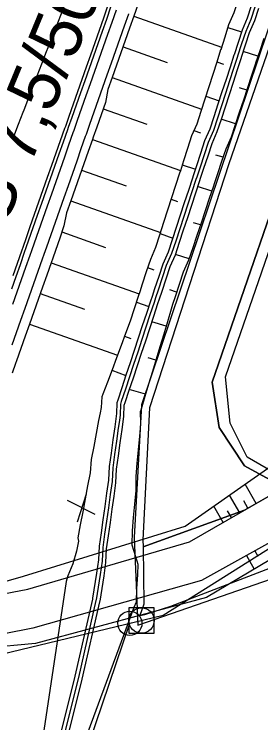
# Model space of a CAD drawing. Extents: x -439827 to -439102, y -1131353 to -1129707.
# Drawn here: x -439604 to -439584.6, y -1130402 to -1130346.4 of the extents above; entities that cross this region are included whole.
import ezdxf

# ---------------------------------------------------------------- set-up
doc = ezdxf.new("R2010")
doc.units = 0
for name, color, linetype in [('Vrstva 1', 7, 'Continuous'), ('Vrstva 10', 7, 'Continuous'), ('Vrstva 11', 7, 'Continuous'), ('Vrstva 13', 7, 'Continuous'), ('Vrstva 15', 7, 'Continuous'), ('Vrstva 2', 7, 'Continuous'), ('Vrstva 29', 7, 'Continuous'), ('Vrstva 4', 7, 'Continuous'), ('Vrstva 44', 7, 'Continuous'), ('Vrstva 45', 7, 'Continuous'), ('Vrstva 52', 7, 'Continuous'), ('Vrstva 8', 7, 'Continuous'), ('Vrstva 9', 7, 'Continuous')]:
    doc.layers.add(name, color=color, linetype=linetype)

msp = doc.modelspace()

# ---------------------------------------------------------------- linework, layer by layer
at = {"layer": 'Vrstva 1'}
for points in [[(-439577.819, -1130295.088), (-439580.971, -1130303.59), (-439578.01, -1130302.539), (-439576.29, -1130302.252), (-439569.317, -1130306.837), (-439584.028, -1130347.627), (-439593.963, -1130377.05), (-439594.536, -1130387.462), (-439594.249, -1130394.34), (-439583.741, -1130390.71), (-439571.132, -1130382.304), (-439541.901, -1130357.085)], [(-439545.626, -1130351.066), (-439561.77, -1130361.383), (-439575.813, -1130377.718), (-439582.499, -1130382.972), (-439585.652, -1130381.157), (-439586.989, -1130378.483), (-439587.371, -1130374.853), (-439572.851, -1130332.916), (-439565.018, -1130320.116), (-439560.242, -1130316.963), (-439559.286, -1130315.53), (-439524.992, -1130313.524)]]:
    msp.add_lwpolyline(points, dxfattribs=at)
at = {"layer": 'Vrstva 10'}
for p, q in [((-439584.948, -1130384.776), (-439585.82, -1130383.256)), ((-439586.25, -1130385.522), (-439587.054, -1130384.12)), ((-439585.6, -1130385.148), (-439585.936, -1130384.564)), ((-439587.55, -1130386.268), (-439588.288, -1130384.984)), ((-439586.9, -1130385.896), (-439587.208, -1130385.358)), ((-439585.056, -1130388.502), (-439584.822, -1130388.926)), ((-439585.712, -1130388.864), (-439585.116, -1130389.944))]:
    msp.add_line(p, q, dxfattribs=at)
at = {"layer": 'Vrstva 11'}
for points in [[(-439614.54, -1130393.736), (-439602.886, -1130391.502), (-439590.194, -1130387.786), (-439581.31, -1130382.686), (-439571.73, -1130375.574), (-439563.408, -1130366.438), (-439554.968, -1130359.058), (-439538.066, -1130350.036), (-439518.176, -1130342.266)], [(-439517.844, -1130344.818), (-439537.232, -1130352.412), (-439553.102, -1130361.278), (-439561.554, -1130368.442), (-439569.834, -1130377.42), (-439579.582, -1130385.476), (-439589.25, -1130390.818), (-439602.494, -1130394.582), (-439614.18, -1130396.886)]]:
    msp.add_lwpolyline(points, dxfattribs=at)
at = {"layer": 'Vrstva 13'}
for p, q in [((-439598.318, -1130384.054), (-439599.028, -1130386.242)), ((-439597.6, -1130385.652), (-439599.772, -1130384.552))]:
    msp.add_line(p, q, dxfattribs=at)
at = {"layer": 'Vrstva 15'}
for p, q in [((-439594.569, -1130346.526), (-439587.676, -1130348.955)), ((-439587.182, -1130347.413), (-439586.104, -1130347.758)), ((-439595.418, -1130348.935), (-439591.938, -1130350.161)), ((-439584.822, -1130349.679), (-439585.975, -1130349.298)), ((-439588.05, -1130350.118), (-439587.518, -1130350.292)), ((-439596.268, -1130351.345), (-439589.241, -1130353.817)), ((-439585.701, -1130352.335), (-439586.272, -1130352.148)), ((-439588.92, -1130352.822), (-439587.869, -1130353.172)), ((-439596.972, -1130353.794), (-439593.544, -1130355.004)), ((-439586.581, -1130354.991), (-439587.713, -1130354.623)), ((-439589.842, -1130355.508), (-439589.322, -1130355.684)), ((-439597.821, -1130356.204), (-439590.902, -1130358.643)), ((-439587.56, -1130357.609), (-439588.119, -1130357.429)), ((-439598.67, -1130358.613), (-439595.18, -1130359.843)), ((-439590.757, -1130358.196), (-439589.735, -1130358.548)), ((-439588.445, -1130360.263), (-439589.552, -1130359.91)), ((-439591.633, -1130360.899), (-439591.129, -1130361.076)), ((-439599.52, -1130361.023), (-439592.479, -1130363.502)), ((-439589.331, -1130362.917), (-439589.879, -1130362.744)), ((-439600.224, -1130363.472), (-439596.792, -1130364.684)), ((-439592.511, -1130363.601), (-439591.515, -1130363.957)), ((-439590.22, -1130365.57), (-439591.304, -1130365.23)), ((-439601.073, -1130365.882), (-439594.152, -1130368.324)), ((-439593.481, -1130366.268), (-439592.991, -1130366.447)), ((-439591.206, -1130368.185), (-439591.741, -1130368.019)), ((-439601.922, -1130368.291), (-439598.444, -1130369.518)), ((-439594.363, -1130368.969), (-439593.397, -1130369.328)), ((-439602.771, -1130370.701), (-439595.843, -1130373.143)), ((-439592.029, -1130370.859), (-439593.158, -1130370.512)), ((-439595.295, -1130371.653), (-439594.794, -1130371.842)), ((-439592.836, -1130373.538), (-439593.438, -1130373.354)), ((-439596.288, -1130374.315), (-439595.192, -1130374.732)), ((-439593.649, -1130376.215), (-439594.925, -1130375.827))]:
    msp.add_line(p, q, dxfattribs=at)
at = {"layer": 'Vrstva 29'}
msp.add_lwpolyline([(-439594.968, -1130394.973), (-439592.968, -1130394.973), (-439592.968, -1130392.973), (-439594.968, -1130392.973)], close=True, dxfattribs=at)
msp.add_lwpolyline([(-439594.968, -1130394.973), (-439592.968, -1130394.973), (-439592.968, -1130392.973), (-439594.968, -1130392.973)], close=True, dxfattribs=at)
msp.add_lwpolyline([(-439645.6, -1130403.853), (-439644.872, -1130403.698), (-439603.72, -1130417.411), (-439603.446, -1130417.268), (-439600.7, -1130411.455), (-439599.692, -1130408.398), (-439594.881, -1130394.192), (-439593.968, -1130393.973)], dxfattribs=at)
msp.add_lwpolyline([(-439645.6, -1130403.853), (-439644.872, -1130403.698), (-439603.72, -1130417.411), (-439603.446, -1130417.268), (-439600.7, -1130411.455), (-439599.692, -1130408.398), (-439594.881, -1130394.192), (-439593.968, -1130393.973)], dxfattribs=at)
for centre, radius in [((-439593.968, -1130393.973), 1), ((-439593.968, -1130393.973), 1), ((-439594.881, -1130394.192), 0.95), ((-439594.881, -1130394.192), 0.95)]:
    msp.add_circle(centre, radius, dxfattribs=at)
at = {"layer": 'Vrstva 4'}
for points in [[(-439559.98, -1130315.123), (-439561.071, -1130316.673), (-439565.58, -1130320.223), (-439568.805, -1130324.53), (-439573.789, -1130332.956), (-439588.419, -1130375.264), (-439587.856, -1130378.814), (-439585.86, -1130381.827), (-439582.761, -1130383.539), (-439582.76, -1130383.539), (-439581.08, -1130382.59), (-439575.74, -1130378.42), (-439561.14, -1130361.82), (-439544.24, -1130351.07), (-439531.53, -1130345.11), (-439529.72, -1130344.26), (-439519.35, -1130339.39), (-439519.98, -1130330.32), (-439521.73, -1130320.56), (-439525.556, -1130312.748), (-439559.98, -1130315.123)], [(-439581.59, -1130342.25), (-439587.1, -1130358.13), (-439593.34, -1130377.27), (-439593.85, -1130387.65), (-439593.84, -1130388.2), (-439585.88, -1130385.3), (-439582.761, -1130383.539), (-439585.86, -1130381.827), (-439587.856, -1130378.814), (-439588.419, -1130375.264), (-439573.789, -1130332.956)], [(-439581.59, -1130342.25), (-439587.1, -1130358.13), (-439593.34, -1130377.27), (-439593.85, -1130387.65), (-439593.84, -1130388.2), (-439585.88, -1130385.3), (-439582.761, -1130383.539), (-439585.86, -1130381.827), (-439587.856, -1130378.814), (-439588.419, -1130375.264), (-439573.789, -1130332.956)], [(-439544.24, -1130351.07), (-439561.14, -1130361.82), (-439575.74, -1130378.42), (-439581.08, -1130382.59), (-439582.761, -1130383.539), (-439585.88, -1130385.3), (-439593.84, -1130388.2), (-439593.78, -1130392.68), (-439594.1, -1130393.57)], [(-439594.1, -1130393.57), (-439593.7, -1130393.5), (-439591.67, -1130392.84), (-439588.25, -1130391.525), (-439583.84, -1130389.83), (-439572.44, -1130382.24), (-439542.04, -1130355.91)]]:
    msp.add_lwpolyline(points, dxfattribs=at)
at = {"layer": 'Vrstva 44'}
msp.add_circle((-439594.881, -1130394.192), 0.95, dxfattribs=at)
at = {"layer": 'Vrstva 45'}
msp.add_lwpolyline([(-439594.968, -1130394.973), (-439592.968, -1130394.973), (-439592.968, -1130392.973), (-439594.968, -1130392.973)], close=True, dxfattribs=at)
msp.add_lwpolyline([(-439645.6, -1130403.853), (-439644.872, -1130403.698), (-439603.72, -1130417.411), (-439603.446, -1130417.268), (-439600.7, -1130411.455), (-439599.692, -1130408.398), (-439594.881, -1130394.192), (-439593.968, -1130393.973)], dxfattribs=at)
msp.add_circle((-439593.968, -1130393.973), 1, dxfattribs=at)
at = {"layer": 'Vrstva 52'}
msp.add_lwpolyline([(-439714.406, -1130412.208), (-439698.562, -1130412.132), (-439686.994, -1130411.394), (-439659.688, -1130406.848), (-439631.008, -1130400.752), (-439604.978, -1130396.618), (-439592.268, -1130393.564), (-439572.812, -1130381.312), (-439556.454, -1130367.154), (-439543.11, -1130355.814), (-439532.998, -1130352.028), (-439506.332, -1130342.096), (-439504.524, -1130343.242), (-439465.198, -1130328.028)], dxfattribs=at)
at = {"layer": 'Vrstva 8'}
for points in [[(-439567.787, -1130292.563), (-439570.478, -1130300.099), (-439571.151, -1130301.984), (-439574.419, -1130311.441), (-439577.66, -1130320.91), (-439581.001, -1130330.339), (-439584.519, -1130339.7), (-439585.609, -1130342.815), (-439585.78, -1130343.353), (-439586.092, -1130344.327), (-439586.403, -1130345.3), (-439586.715, -1130346.274), (-439587.117, -1130347.212), (-439587.429, -1130348.185), (-439587.742, -1130349.159), (-439587.747, -1130349.174), (-439588.054, -1130350.132), (-439588.367, -1130351.105), (-439588.68, -1130352.078), (-439588.994, -1130353.051), (-439589.307, -1130354.024), (-439589.621, -1130354.996)], [(-439596.391, -1130345.832), (-439596.726, -1130346.78), (-439597.065, -1130347.743), (-439597.404, -1130348.706), (-439597.744, -1130349.669), (-439598.083, -1130350.632), (-439598.422, -1130351.594), (-439598.762, -1130352.557), (-439599.101, -1130353.52), (-439599.44, -1130354.483), (-439599.717, -1130355.268), (-439599.78, -1130355.446), (-439600.119, -1130356.409), (-439600.458, -1130357.371), (-439600.798, -1130358.334), (-439601.137, -1130359.297), (-439601.476, -1130360.26), (-439601.815, -1130361.223), (-439602.155, -1130362.185), (-439602.494, -1130363.148), (-439602.833, -1130364.111), (-439603.042, -1130364.704), (-439603.173, -1130365.074), (-439603.512, -1130366.037), (-439603.851, -1130367), (-439604.191, -1130367.962)], [(-439594.228, -1130345.558), (-439594.567, -1130346.521), (-439594.573, -1130346.535), (-439594.907, -1130347.483), (-439595.246, -1130348.446), (-439595.585, -1130349.409), (-439595.925, -1130350.372), (-439596.264, -1130351.335), (-439596.603, -1130352.297), (-439596.803, -1130353.314), (-439597.142, -1130354.277), (-439597.481, -1130355.24), (-439597.758, -1130356.025), (-439597.821, -1130356.203), (-439598.16, -1130357.166), (-439598.499, -1130358.128), (-439598.839, -1130359.091), (-439599.178, -1130360.054), (-439599.517, -1130361.017), (-439599.857, -1130361.98), (-439600.056, -1130362.997), (-439600.395, -1130363.959), (-439600.735, -1130364.922), (-439600.944, -1130365.515), (-439601.074, -1130365.885), (-439601.413, -1130366.848), (-439601.753, -1130367.811), (-439602.092, -1130368.774), (-439602.431, -1130369.736), (-439602.771, -1130370.699), (-439603.11, -1130371.662), (-439603.449, -1130372.625), (-439603.789, -1130373.588), (-439603.864, -1130373.803), (-439604.119, -1130374.554)], [(-439596.625, -1130345.742), (-439596.959, -1130346.69), (-439597.298, -1130347.653), (-439597.637, -1130348.616), (-439597.977, -1130349.579), (-439598.316, -1130350.541), (-439598.655, -1130351.504), (-439598.995, -1130352.467), (-439599.334, -1130353.43), (-439599.673, -1130354.393), (-439599.95, -1130355.178), (-439600.013, -1130355.356), (-439600.352, -1130356.318), (-439600.691, -1130357.281), (-439601.031, -1130358.244), (-439601.37, -1130359.207), (-439601.709, -1130360.17), (-439602.049, -1130361.132), (-439602.388, -1130362.095), (-439602.727, -1130363.058), (-439603.067, -1130364.021), (-439603.276, -1130364.614), (-439603.406, -1130364.984), (-439603.745, -1130365.947), (-439604.085, -1130366.909)], [(-439599.973, -1130345.525), (-439600.34, -1130346.477), (-439600.708, -1130347.429), (-439601.076, -1130348.381), (-439601.444, -1130349.332), (-439601.812, -1130350.284), (-439602.18, -1130351.236), (-439602.548, -1130352.188), (-439602.916, -1130353.14), (-439603.216, -1130353.916), (-439603.284, -1130354.091), (-439603.651, -1130355.043), (-439604.019, -1130355.995)], [(-439585.335, -1130345.713), (-439585.65, -1130346.685), (-439586.059, -1130347.621), (-439586.376, -1130348.593), (-439586.692, -1130349.565), (-439586.697, -1130349.58), (-439587.009, -1130350.536), (-439587.325, -1130351.508), (-439587.643, -1130352.479), (-439587.96, -1130353.45), (-439588.277, -1130354.422), (-439588.595, -1130355.393), (-439589.007, -1130356.328), (-439589.325, -1130357.299), (-439589.644, -1130358.269), (-439589.904, -1130359.061), (-439589.962, -1130359.24), (-439590.281, -1130360.211), (-439590.601, -1130361.181), (-439590.92, -1130362.152)], [(-439585.055, -1130345.821), (-439585.37, -1130346.793), (-439585.78, -1130347.729), (-439586.096, -1130348.701), (-439586.412, -1130349.673), (-439586.417, -1130349.688), (-439586.729, -1130350.644), (-439587.046, -1130351.616), (-439587.363, -1130352.587), (-439587.68, -1130353.559), (-439587.998, -1130354.53), (-439588.315, -1130355.501), (-439588.727, -1130356.436), (-439589.045, -1130357.407), (-439589.364, -1130358.378), (-439589.624, -1130359.169), (-439589.683, -1130359.348), (-439590.002, -1130360.319), (-439590.321, -1130361.29), (-439590.64, -1130362.26)], [(-439584.775, -1130345.93), (-439585.091, -1130346.902), (-439585.5, -1130347.837), (-439585.816, -1130348.809), (-439586.132, -1130349.781), (-439586.137, -1130349.796), (-439586.449, -1130350.752), (-439586.766, -1130351.724), (-439587.083, -1130352.695), (-439587.4, -1130353.667), (-439587.718, -1130354.638), (-439588.036, -1130355.609), (-439588.447, -1130356.544), (-439588.765, -1130357.515), (-439589.084, -1130358.486), (-439589.344, -1130359.277), (-439589.403, -1130359.457), (-439589.722, -1130360.427), (-439590.041, -1130361.398), (-439590.361, -1130362.368)], [(-439594.987, -1130346.358), (-439594.992, -1130346.373), (-439595.326, -1130347.321), (-439595.666, -1130348.284), (-439596.005, -1130349.247), (-439596.344, -1130350.21), (-439596.684, -1130351.172), (-439597.023, -1130352.135), (-439597.362, -1130353.098), (-439597.702, -1130354.061), (-439598.041, -1130355.024), (-439598.318, -1130355.809), (-439598.38, -1130355.986), (-439598.72, -1130356.949), (-439599.059, -1130357.912), (-439599.398, -1130358.875), (-439599.738, -1130359.838), (-439600.077, -1130360.801), (-439600.416, -1130361.763), (-439600.756, -1130362.726), (-439601.095, -1130363.689), (-439601.434, -1130364.652), (-439601.643, -1130365.244), (-439601.774, -1130365.615), (-439602.113, -1130366.578), (-439602.452, -1130367.54), (-439602.792, -1130368.503), (-439603.131, -1130369.466), (-439603.47, -1130370.429), (-439603.81, -1130371.392), (-439604.149, -1130372.354)], [(-439604.074, -1130369.134), (-439603.735, -1130368.171), (-439603.396, -1130367.208), (-439603.056, -1130366.245), (-439602.717, -1130365.283), (-439602.586, -1130364.912), (-439602.378, -1130364.32), (-439602.038, -1130363.357), (-439601.699, -1130362.394), (-439601.36, -1130361.431), (-439601.02, -1130360.468), (-439600.681, -1130359.506), (-439600.342, -1130358.543), (-439600.002, -1130357.58), (-439599.663, -1130356.617), (-439599.324, -1130355.654), (-439599.261, -1130355.476), (-439598.984, -1130354.692), (-439598.645, -1130353.729), (-439598.306, -1130352.766), (-439597.966, -1130351.803), (-439597.627, -1130350.84), (-439597.288, -1130349.877), (-439596.948, -1130348.915), (-439596.609, -1130347.952), (-439596.27, -1130346.989), (-439595.935, -1130346.041)], [(-439584.359, -1130348.278), (-439584.679, -1130349.248), (-439585, -1130350.219), (-439585.005, -1130350.234), (-439585.321, -1130351.188), (-439585.642, -1130352.158), (-439585.963, -1130353.128), (-439586.285, -1130354.098), (-439586.607, -1130355.067), (-439586.929, -1130356.037), (-439587.347, -1130356.969), (-439587.67, -1130357.938), (-439587.993, -1130358.908), (-439588.256, -1130359.698), (-439588.316, -1130359.877), (-439588.639, -1130360.846), (-439588.963, -1130361.815), (-439589.287, -1130362.783), (-439589.611, -1130363.752), (-439589.935, -1130364.721), (-439590.26, -1130365.689), (-439590.681, -1130366.62), (-439591.006, -1130367.589), (-439591.331, -1130368.557), (-439591.527, -1130369.155), (-439591.638, -1130369.532), (-439591.927, -1130370.515), (-439592.218, -1130371.496), (-439592.514, -1130372.476), (-439592.811, -1130373.455), (-439593.108, -1130374.434), (-439593.405, -1130375.413), (-439593.703, -1130376.392), (-439593.997, -1130377.373), (-439594.059, -1130377.593), (-439594.036, -1130378.451), (-439594.076, -1130378.89), (-439594.132, -1130379.508), (-439594.227, -1130380.565), (-439594.323, -1130381.622), (-439594.42, -1130382.679), (-439594.419, -1130383.773), (-439594.516, -1130384.83), (-439594.613, -1130385.886), (-439594.71, -1130386.943), (-439594.721, -1130388.032), (-439594.332, -1130389.277), (-439594.244, -1130389.546), (-439594.286, -1130390.388), (-439594.36, -1130391.454), (-439594.377, -1130392.541), (-439594.567, -1130392.957), (-439600.362, -1130408.624)], [(-439589.621, -1130354.996), (-439590.026, -1130355.934), (-439590.34, -1130356.906), (-439590.655, -1130357.879), (-439590.911, -1130358.672), (-439590.969, -1130358.851), (-439591.284, -1130359.823), (-439591.6, -1130360.795), (-439591.915, -1130361.767), (-439592.231, -1130362.739), (-439592.547, -1130363.711), (-439592.863, -1130364.683), (-439593.27, -1130365.62), (-439593.586, -1130366.591), (-439593.903, -1130367.563), (-439594.098, -1130368.161), (-439594.22, -1130368.534), (-439594.538, -1130369.506), (-439594.868, -1130370.472), (-439595.215, -1130371.432), (-439595.56, -1130372.392), (-439595.92, -1130373.347), (-439596.283, -1130374.301), (-439596.645, -1130375.255), (-439597.008, -1130376.208), (-439597.089, -1130376.422), (-439597.147, -1130377.249), (-439597.226, -1130377.673), (-439597.337, -1130378.269), (-439597.527, -1130379.29), (-439597.718, -1130380.31), (-439597.909, -1130381.33), (-439598.01, -1130382.385), (-439598.201, -1130383.405), (-439598.393, -1130384.425), (-439598.585, -1130385.445), (-439598.777, -1130386.465), (-439598.969, -1130387.484), (-439598.92, -1130387.739), (-439599.071, -1130388.539), (-439599.368, -1130389.518), (-439599.747, -1130390.465), (-439599.891, -1130390.899), (-439602.421, -1130407.828)], [(-439590.92, -1130362.152), (-439591.24, -1130363.122), (-439591.56, -1130364.093), (-439591.88, -1130365.063), (-439592.294, -1130365.997), (-439592.615, -1130366.967), (-439592.936, -1130367.937), (-439593.133, -1130368.534), (-439593.257, -1130368.907), (-439593.578, -1130369.876), (-439593.9, -1130370.846), (-439594.222, -1130371.815), (-439594.544, -1130372.785), (-439594.867, -1130373.754), (-439595.189, -1130374.724), (-439595.512, -1130375.693), (-439595.836, -1130376.662), (-439595.908, -1130376.879), (-439595.926, -1130377.721), (-439595.986, -1130378.152), (-439596.071, -1130378.759), (-439596.215, -1130379.797), (-439596.36, -1130380.835), (-439596.506, -1130381.873), (-439596.558, -1130382.946), (-439596.704, -1130383.984), (-439596.849, -1130385.022), (-439596.996, -1130386.059), (-439597.142, -1130387.097), (-439597.289, -1130388.134), (-439597.342, -1130389.207), (-439597.49, -1130390.244), (-439597.804, -1130392.227), (-439597.828, -1130392.301), (-439599.207, -1130398.349), (-439601.651, -1130408.125)], [(-439590.64, -1130362.26), (-439590.96, -1130363.23), (-439591.28, -1130364.201), (-439591.6, -1130365.171), (-439592.014, -1130366.105), (-439592.335, -1130367.075), (-439592.656, -1130368.045), (-439592.854, -1130368.642), (-439592.977, -1130369.015), (-439593.299, -1130369.984), (-439593.62, -1130370.954), (-439593.942, -1130371.924), (-439594.264, -1130372.893), (-439594.587, -1130373.862), (-439594.91, -1130374.832), (-439595.233, -1130375.801), (-439595.556, -1130376.77), (-439595.628, -1130376.987), (-439595.646, -1130377.829), (-439595.706, -1130378.26), (-439595.791, -1130378.867), (-439595.936, -1130379.905), (-439596.08, -1130380.943), (-439596.226, -1130381.981), (-439596.278, -1130383.055), (-439596.424, -1130384.092), (-439596.57, -1130385.13), (-439596.716, -1130386.167), (-439596.862, -1130387.205), (-439597.009, -1130388.242), (-439597.063, -1130389.315), (-439597.21, -1130390.352), (-439597.524, -1130392.336), (-439597.548, -1130392.41), (-439598.927, -1130398.457), (-439601.372, -1130408.233)], [(-439590.361, -1130362.368), (-439590.68, -1130363.339), (-439591, -1130364.309), (-439591.321, -1130365.279), (-439591.734, -1130366.213), (-439592.055, -1130367.183), (-439592.376, -1130368.153), (-439592.574, -1130368.75), (-439592.697, -1130369.123), (-439593.019, -1130370.093), (-439593.341, -1130371.062), (-439593.662, -1130372.032), (-439593.985, -1130373.001), (-439594.307, -1130373.971), (-439594.63, -1130374.94), (-439594.953, -1130375.909), (-439595.276, -1130376.878), (-439595.348, -1130377.095), (-439595.367, -1130377.937), (-439595.427, -1130378.368), (-439595.511, -1130378.975), (-439595.656, -1130380.013), (-439595.801, -1130381.051), (-439595.946, -1130382.089), (-439595.998, -1130383.163), (-439596.144, -1130384.2), (-439596.29, -1130385.238), (-439596.436, -1130386.276), (-439596.583, -1130387.313), (-439596.729, -1130388.35), (-439596.783, -1130389.423), (-439596.93, -1130390.461), (-439597.244, -1130392.444), (-439597.268, -1130392.518), (-439598.647, -1130398.565), (-439601.092, -1130408.342)]]:
    msp.add_lwpolyline(points, dxfattribs=at)
at = {"layer": 'Vrstva 9'}
for points in [[(-439614.54, -1130393.736), (-439603.236, -1130390.488), (-439590.542, -1130386.564), (-439573.232, -1130374.44), (-439556.462, -1130357.56), (-439538.37, -1130348.624), (-439517.466, -1130339.712)], [(-439517.528, -1130346.522), (-439536.884, -1130354.376), (-439551.674, -1130362.86), (-439567.784, -1130379.662), (-439588.862, -1130392.166), (-439602.298, -1130395.778), (-439614.18, -1130396.886)]]:
    msp.add_lwpolyline(points, dxfattribs=at)

# ---------------------------------------------------------------- texts
at = {"layer": 'Vrstva 2'}
msp.add_text('S 7,5/50', height=4, rotation=67.5206, dxfattribs=at).set_placement((-439604.675, -1130363.042))

doc.saveas('drawing.dxf')
